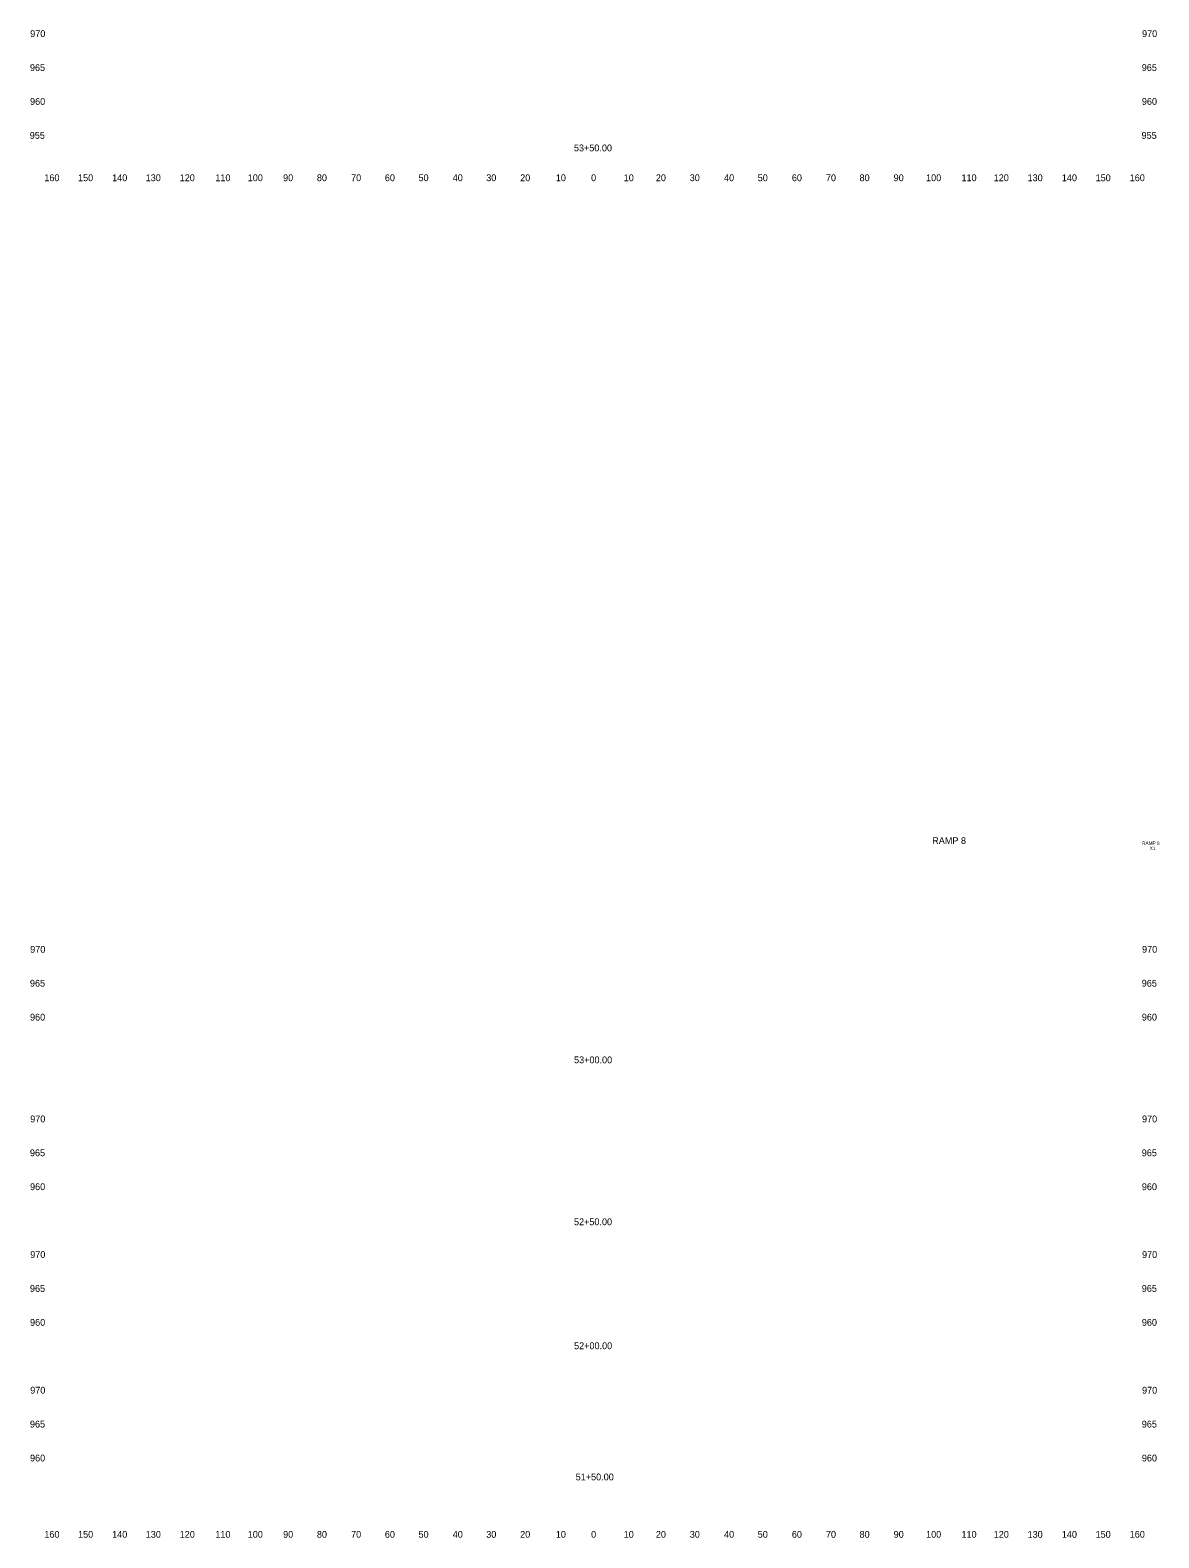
# Model space of a CAD drawing. Extents: x 4994 to 5843, y 4997 to 8804.
# Drawn here: x 4993.9 to 5326.7, y 4997.5 to 5442 of the extents above; entities that cross this region are included whole.
import ezdxf

# ---------------------------------------------------------------- set-up
doc = ezdxf.new("R2010")
doc.units = 0
for name, color, linetype in [('RD_SHT_ID', 7, 'Continuous'), ('RD_XS_TX_Offset', 7, 'Continuous'), ('RD_XS_TX_Station', 7, 'Continuous')]:
    doc.layers.add(name, color=color, linetype=linetype)

msp = doc.modelspace()

# ---------------------------------------------------------------- texts
at = {"layer": 'RD_SHT_ID'}
for s, height, p in [('RAMP 8', 2, (5259.88, 5202.06)), ('RAMP 8', 1, (5321.78, 5201.8)), ('X1', 1, (5324.02, 5200.3))]:
    msp.add_text(s, height=height, dxfattribs=at).set_placement(p)
at = {"layer": 'RD_XS_TX_Offset'}
for s, p in [('970', (4993.94, 5440)), ('970', (5321.74, 5440)), ('965', (4993.86, 5430)), ('965', (5321.66, 5430)), ('960', (4993.89, 5420)), ('960', (5321.69, 5420)), ('955', (4993.8, 5410)), ('955', (5321.6, 5410)), ('160', (4998.1, 5397.5)), ('150', (5008.04, 5397.5)), ('140', (5018.1, 5397.5)), ('130', (5027.99, 5397.5)), ('120', (5038.01, 5397.5)), ('110', (5048.51, 5397.5)), ('100', (5058.07, 5397.5)), ('90', (5068.5, 5397.5)), ('80', (5078.46, 5397.5)), ('70', (5088.54, 5397.5)), ('60', (5098.5, 5397.5)), ('50', (5108.43, 5397.5)), ('40', (5118.5, 5397.5)), ('30', (5128.39, 5397.5)), ('20', (5138.4, 5397.5)), ('10', (5148.91, 5397.5)), ('0', (5159.3, 5397.5)), ('0', (5159.3, 5397.5)), ('10', (5168.91, 5397.5)), ('20', (5178.4, 5397.5)), ('30', (5188.39, 5397.5)), ('40', (5198.5, 5397.5)), ('50', (5208.43, 5397.5)), ('60', (5218.5, 5397.5)), ('70', (5228.54, 5397.5)), ('80', (5238.46, 5397.5)), ('90', (5248.5, 5397.5)), ('100', (5258.07, 5397.5)), ('110', (5268.51, 5397.5)), ('120', (5278.01, 5397.5)), ('130', (5287.99, 5397.5)), ('140', (5298.1, 5397.5)), ('150', (5308.04, 5397.5)), ('160', (5318.1, 5397.5)), ('970', (4993.94, 5170)), ('970', (5321.74, 5170)), ('965', (4993.86, 5160)), ('965', (5321.66, 5160)), ('960', (4993.89, 5150)), ('960', (5321.69, 5150)), ('970', (4993.94, 5120)), ('970', (5321.74, 5120)), ('965', (4993.86, 5110)), ('965', (5321.66, 5110)), ('960', (4993.89, 5100)), ('960', (5321.69, 5100)), ('970', (4993.94, 5080)), ('970', (5321.74, 5080)), ('965', (4993.86, 5070)), ('965', (5321.66, 5070)), ('960', (4993.89, 5060)), ('960', (5321.69, 5060)), ('970', (4993.94, 5040)), ('970', (5321.74, 5040)), ('965', (4993.86, 5030)), ('965', (5321.66, 5030)), ('960', (4993.89, 5020)), ('960', (5321.69, 5020)), ('160', (4998.1, 4997.5)), ('150', (5008.04, 4997.5)), ('140', (5018.1, 4997.5)), ('130', (5027.99, 4997.5)), ('120', (5038.01, 4997.5)), ('110', (5048.51, 4997.5)), ('100', (5058.07, 4997.5)), ('90', (5068.5, 4997.5)), ('80', (5078.46, 4997.5)), ('70', (5088.54, 4997.5)), ('60', (5098.5, 4997.5)), ('50', (5108.43, 4997.5)), ('40', (5118.5, 4997.5)), ('30', (5128.39, 4997.5)), ('20', (5138.4, 4997.5)), ('10', (5148.91, 4997.5)), ('0', (5159.3, 4997.5)), ('0', (5159.3, 4997.5)), ('10', (5168.91, 4997.5)), ('20', (5178.4, 4997.5)), ('30', (5188.39, 4997.5)), ('40', (5198.5, 4997.5)), ('50', (5208.43, 4997.5)), ('60', (5218.5, 4997.5)), ('70', (5228.54, 4997.5)), ('80', (5238.46, 4997.5)), ('90', (5248.5, 4997.5)), ('100', (5258.07, 4997.5)), ('110', (5268.51, 4997.5)), ('120', (5278.01, 4997.5)), ('130', (5287.99, 4997.5)), ('140', (5298.1, 4997.5)), ('150', (5308.04, 4997.5)), ('160', (5318.1, 4997.5))]:
    msp.add_text(s, height=2, dxfattribs=at).set_placement(p)
at = {"layer": 'RD_XS_TX_Station'}
for s, p in [('53+50.00', (5154.24, 5406.31)), ('53+00.00', (5154.28, 5137.41)), ('52+50.00', (5154.26, 5089.66)), ('52+00.00', (5154.29, 5053.1)), ('51+50.00', (5154.76, 5014.43))]:
    msp.add_text(s, height=2, dxfattribs=at).set_placement(p)

doc.saveas('drawing.dxf')
